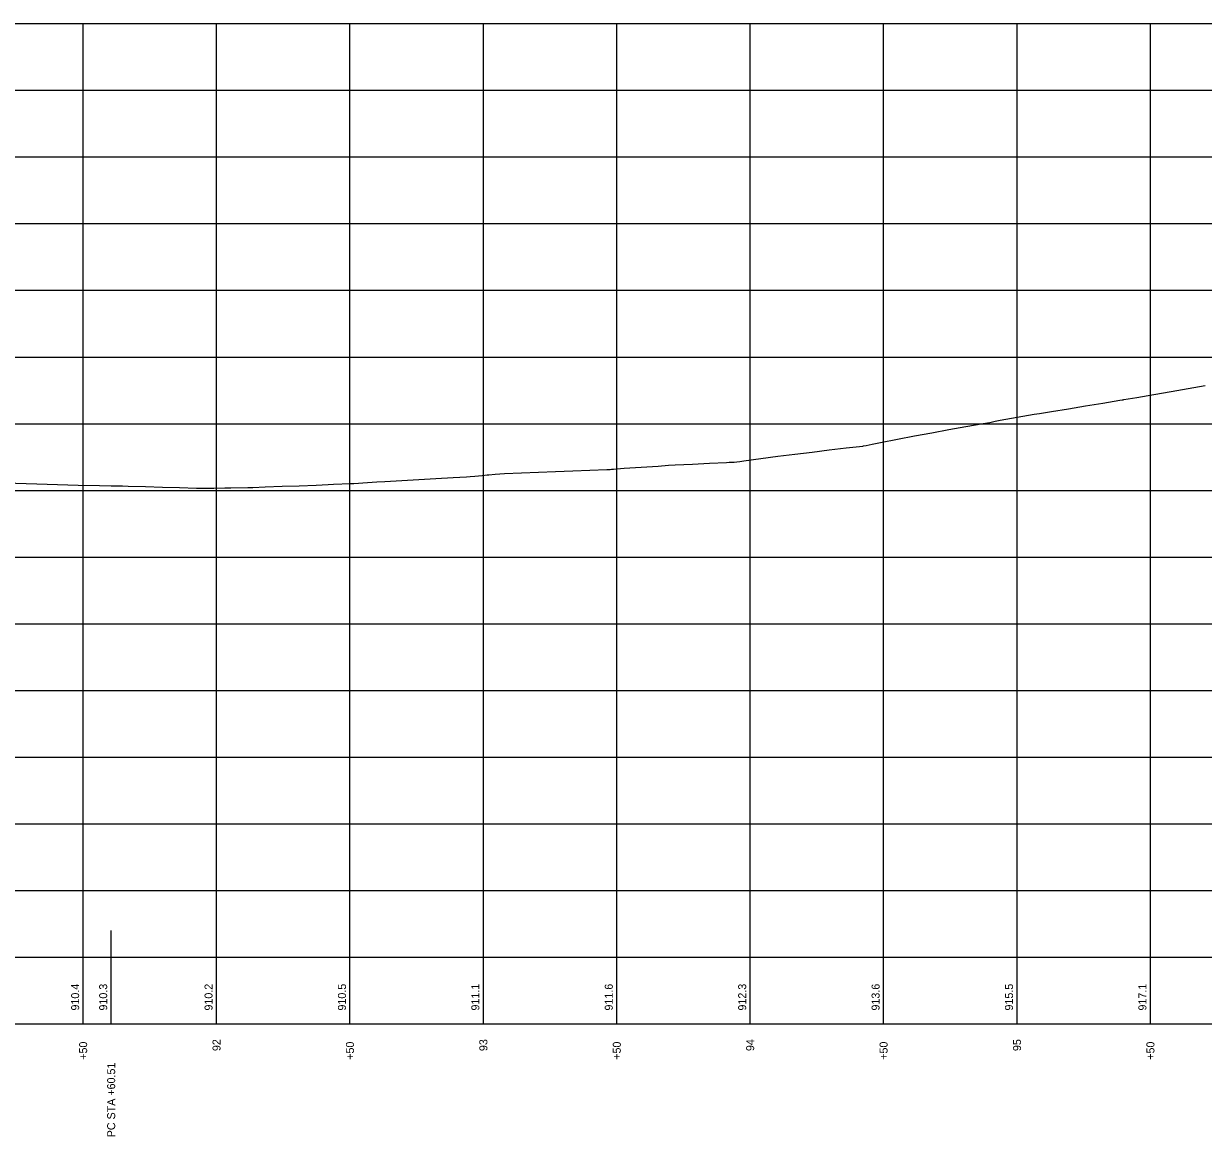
# Model space of a CAD drawing. Extents: x 76292 to 78417, y 50412 to 52585.
# Drawn here: x 77533 to 77975.2, y 51118.2 to 51535.3 of the extents above; entities that cross this region are included whole.
import ezdxf

# ---------------------------------------------------------------- set-up
doc = ezdxf.new("R2010")
doc.units = 0
for name, color, linetype in [('1', 7, 'Continuous'), ('2', 7, 'Continuous'), ('3', 7, 'Continuous'), ('33', 7, 'Continuous'), ('63', 7, 'Continuous')]:
    doc.layers.add(name, color=color, linetype=linetype)

msp = doc.modelspace()

# ---------------------------------------------------------------- linework, layer by layer
at = {"layer": '1'}
for p, q in [((76305.34, 51160.35), (78405.34, 51160.35)), ((77555.34, 51160.35), (77555.34, 51160.35)), ((77605.34, 51160.35), (77605.34, 51160.35)), ((77655.34, 51160.35), (77655.34, 51160.35)), ((77705.34, 51160.35), (77705.34, 51160.35)), ((77755.34, 51160.35), (77755.34, 51160.35)), ((77805.34, 51160.35), (77805.34, 51160.35)), ((77855.34, 51160.35), (77855.34, 51160.35)), ((77905.34, 51160.35), (77905.34, 51160.35)), ((77955.34, 51160.35), (77955.34, 51160.35))]:
    msp.add_line(p, q, dxfattribs=at)
for points in [[(77555.34, 51160.35), (77555.34, 51195.35)], [(77555.34, 51160.35), (77555.34, 51195.35)], [(77555.34, 51160.35), (77555.34, 51195.35)], [(77555.34, 51160.35), (77555.34, 51195.35)], [(77565.85, 51160.35), (77565.85, 51195.35)], [(77565.85, 51160.35), (77565.85, 51195.35)], [(77565.85, 51160.35), (77565.85, 51195.35)], [(77565.85, 51160.35), (77565.85, 51195.35)], [(77605.34, 51160.35), (77605.34, 51195.35)], [(77605.34, 51160.35), (77605.34, 51195.35)], [(77605.34, 51160.35), (77605.34, 51195.35)], [(77605.34, 51160.35), (77605.34, 51195.35)], [(77655.34, 51160.35), (77655.34, 51195.35)], [(77655.34, 51160.35), (77655.34, 51195.35)], [(77655.34, 51160.35), (77655.34, 51195.35)], [(77655.34, 51160.35), (77655.34, 51195.35)], [(77705.34, 51160.35), (77705.34, 51195.35)], [(77705.34, 51160.35), (77705.34, 51195.35)], [(77705.34, 51160.35), (77705.34, 51195.35)], [(77705.34, 51160.35), (77705.34, 51195.35)], [(77755.34, 51160.35), (77755.34, 51195.35)], [(77755.34, 51160.35), (77755.34, 51195.35)], [(77755.34, 51160.35), (77755.34, 51195.35)], [(77755.34, 51160.35), (77755.34, 51195.35)], [(77805.34, 51160.35), (77805.34, 51195.35)], [(77805.34, 51160.35), (77805.34, 51195.35)], [(77805.34, 51160.35), (77805.34, 51195.35)], [(77805.34, 51160.35), (77805.34, 51195.35)], [(77855.34, 51160.35), (77855.34, 51195.35)], [(77855.34, 51160.35), (77855.34, 51195.35)], [(77855.34, 51160.35), (77855.34, 51195.35)], [(77855.34, 51160.35), (77855.34, 51195.35)], [(77905.34, 51160.35), (77905.34, 51195.35)], [(77905.34, 51160.35), (77905.34, 51195.35)], [(77905.34, 51160.35), (77905.34, 51195.35)], [(77905.34, 51160.35), (77905.34, 51195.35)], [(77955.34, 51160.35), (77955.34, 51195.35)], [(77955.34, 51160.35), (77955.34, 51195.35)], [(77955.34, 51160.35), (77955.34, 51195.35)], [(77955.34, 51160.35), (77955.34, 51195.35)]]:
    msp.add_lwpolyline(points, dxfattribs=at)
at = {"layer": '2'}
msp.add_lwpolyline([(77518.31, 51363.45), (77553.52, 51362.31), (77561.48, 51362.15), (77565.85, 51362.09), (77570.14, 51362.04), (77572.26, 51361.98), (77578.66, 51361.77), (77585.07, 51361.58), (77591.48, 51361.39), (77597.88, 51361.22), (77598.48, 51361.2), (77604.29, 51361.23), (77608.47, 51361.26), (77610.7, 51361.3), (77617.11, 51361.43), (77618.89, 51361.47), (77623.51, 51361.63), (77629.92, 51361.87), (77636.33, 51362.11), (77642.73, 51362.35), (77647.17, 51362.53), (77649.14, 51362.62), (77655.55, 51362.9), (77656.82, 51362.96), (77661.95, 51363.32), (77665.36, 51363.56), (77668.36, 51363.72), (77674.77, 51364.08), (77681.18, 51364.43), (77687.58, 51364.8), (77693.99, 51365.16), (77699, 51365.45), (77700.4, 51365.57), (77702.11, 51365.72), (77704.87, 51365.98), (77706.8, 51366.17), (77707.41, 51366.23), (77709.77, 51366.48), (77713.21, 51366.62), (77719.62, 51366.88), (77726.02, 51367.14), (77732.43, 51367.39), (77738.84, 51367.64), (77745.25, 51367.89), (77751.65, 51368.14), (77752.43, 51368.17), (77752.92, 51368.22), (77753.35, 51368.26), (77753.73, 51368.3), (77754.09, 51368.34), (77758.06, 51368.62), (77764.47, 51369.06), (77770.87, 51369.49), (77774.73, 51369.75), (77777.28, 51369.89), (77783.69, 51370.24), (77790.09, 51370.55), (77796.5, 51370.85), (77797.44, 51370.89), (77798.34, 51370.91), (77799.32, 51370.97), (77800.38, 51371.06), (77801.41, 51371.2), (77802.91, 51371.41), (77809.32, 51372.28), (77815.72, 51373.13), (77822.13, 51373.95), (77828.54, 51374.74), (77834.94, 51375.51), (77841.35, 51376.25), (77846.33, 51376.8), (77847.53, 51376.96), (77847.76, 51377), (77848.76, 51377.17), (77849.92, 51377.4), (77851.01, 51377.65), (77854.17, 51378.28), (77860.57, 51379.52), (77866.98, 51380.75), (77873.39, 51381.95), (77879.79, 51383.13), (77886.2, 51384.29), (77892.61, 51385.42), (77895.13, 51385.86), (77895.65, 51385.97), (77896.16, 51386.09), (77896.68, 51386.2), (77897.17, 51386.3), (77899.01, 51386.63), (77905.42, 51387.76), (77911.83, 51388.87), (77913.74, 51389.2), (77918.24, 51389.93), (77924.64, 51390.98), (77931.05, 51392.03), (77937.46, 51393.08), (77943.86, 51394.12), (77944.77, 51394.27), (77944.94, 51394.29), (77945.11, 51394.31), (77945.44, 51394.36), (77950.27, 51395.18), (77956.68, 51396.28), (77963.08, 51397.39), (77969.49, 51398.5), (77975.9, 51399.61)], dxfattribs=at)
at = {"layer": '63'}
for p, q in [((76305.34, 51535.35), (78405.34, 51535.35)), ((76305.34, 51535.35), (78405.34, 51535.35)), ((77555.34, 51160.35), (77555.34, 51535.35)), ((77605.34, 51160.35), (77605.34, 51535.35)), ((77655.34, 51160.35), (77655.34, 51535.35)), ((77705.34, 51160.35), (77705.34, 51535.35)), ((77755.34, 51160.35), (77755.34, 51535.35)), ((77805.34, 51160.35), (77805.34, 51535.35)), ((77855.34, 51160.35), (77855.34, 51535.35)), ((77905.34, 51160.35), (77905.34, 51535.35)), ((77955.34, 51160.35), (77955.34, 51535.35)), ((76305.34, 51510.35), (78405.34, 51510.35)), ((76305.34, 51485.35), (78405.34, 51485.35)), ((76305.34, 51460.35), (78405.34, 51460.35)), ((76305.34, 51435.35), (78405.34, 51435.35)), ((76305.34, 51410.35), (78405.34, 51410.35)), ((76305.34, 51385.35), (78405.34, 51385.35)), ((76305.34, 51360.35), (78405.34, 51360.35)), ((76305.34, 51335.35), (78405.34, 51335.35)), ((76305.34, 51310.35), (78405.34, 51310.35)), ((76305.34, 51285.35), (78405.34, 51285.35)), ((76305.34, 51260.35), (78405.34, 51260.35)), ((76305.34, 51235.35), (78405.34, 51235.35)), ((76305.34, 51210.35), (78405.34, 51210.35)), ((76305.34, 51185.35), (78405.34, 51185.35))]:
    msp.add_line(p, q, dxfattribs=at)

# ---------------------------------------------------------------- texts
at = {"layer": '1'}
for s, p in [('+50', (77556.84, 51146.89)), ('92', (77606.84, 51150.15)), ('+50', (77656.84, 51146.89)), ('93', (77706.84, 51150.15)), ('+50', (77756.84, 51146.89)), ('94', (77806.84, 51150.15)), ('+50', (77856.84, 51146.89)), ('95', (77906.84, 51150.15)), ('+50', (77956.84, 51146.89))]:
    msp.add_text(s, height=3, rotation=90, dxfattribs=at).set_placement(p)
at = {"layer": '3'}
for s, p in [('910.4', (77553.84, 51165.35)), ('910.3', (77564.35, 51165.35)), ('910.2', (77603.84, 51165.35)), ('910.5', (77653.84, 51165.35)), ('911.1', (77703.84, 51165.35)), ('911.6', (77753.84, 51165.35)), ('912.3', (77803.84, 51165.35)), ('913.6', (77853.84, 51165.35)), ('915.5', (77903.84, 51165.35)), ('917.1', (77953.84, 51165.35))]:
    msp.add_text(s, height=3, rotation=90, dxfattribs=at).set_placement(p)
at = {"layer": '33'}
msp.add_text('PC STA +60.51', height=3, rotation=90, dxfattribs=at).set_placement((77567.35, 51117.83))

doc.saveas('drawing.dxf')
